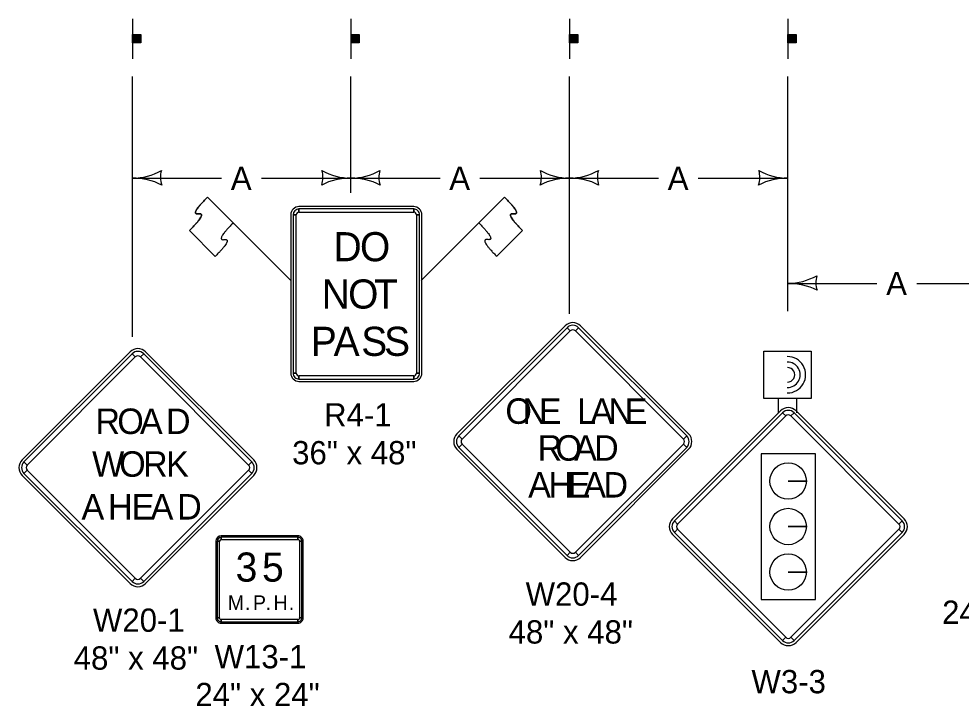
# Model space of a CAD drawing. Extents: x 10124 to 16850, y 7924 to 12166.
# Drawn here: x 13696 to 14343, y 8822 to 9294 of the extents above; entities that cross this region are included whole.
import ezdxf

# ---------------------------------------------------------------- set-up
doc = ezdxf.new("R2010")
doc.units = 0
for name, color, linetype in [('dsnStdLabel', 7, 'Continuous'), ('Level 2', 7, 'Continuous'), ('Level 5', 7, 'Continuous')]:
    doc.layers.add(name, color=color, linetype=linetype)

msp = doc.modelspace()

# ---------------------------------------------------------------- linework, layer by layer
at = {"layer": 'dsnStdLabel'}
for p, q in [((13883.12, 9114.52), (13825.78, 9171.82)), ((13825.78, 9171.82), (13843.47, 9154.14)), ((13972.41, 9114.52), (14029.73, 9171.84)), ((14029.73, 9171.84), (14012.05, 9154.15)), ((13967.36, 9165.28), (13888.61, 9165.28)), ((13888.61, 9161.53), (13888.61, 9163.72)), ((13967.36, 9163.72), (13967.36, 9161.53)), ((13882.98, 9159.65), (13882.98, 9050.9)), ((13884.55, 9159.65), (13886.73, 9159.65)), ((13969.23, 9159.65), (13971.42, 9159.65)), ((13972.98, 9050.9), (13972.98, 9159.65)), ((13831.09, 9131.15), (13813.41, 9148.83)), ((14024.43, 9131.17), (14042.11, 9148.85)), ((14071.32, 9083.47), (13997.07, 9009.22)), ((14072.64, 9082.14), (14074.85, 9079.93)), ((14078.39, 9079.93), (14080.6, 9082.14)), ((14156.17, 9009.22), (14081.92, 9083.47)), ((13772.7, 9065.55), (13698.45, 8991.3)), ((13857.55, 8991.3), (13783.31, 9065.55)), ((13774.03, 9064.22), (13776.24, 9062.01)), ((13779.77, 9062.01), (13781.98, 9064.22)), ((13886.73, 9050.9), (13884.55, 9050.9)), ((13888.61, 9046.84), (13888.61, 9049.03)), ((13967.36, 9049.03), (13967.36, 9046.84)), ((13971.42, 9050.9), (13969.23, 9050.9)), ((13888.61, 9045.28), (13967.36, 9045.28)), ((14219.28, 9025.04), (14145.03, 8950.79)), ((14220.61, 9023.71), (14222.82, 9021.5)), ((14226.35, 9021.5), (14228.56, 9023.71)), ((14304.13, 8950.79), (14229.89, 9025.04)), ((14000.6, 9005.68), (13998.4, 9007.89)), ((14154.84, 9007.89), (14152.63, 9005.68)), ((13998.4, 8999.94), (14000.6, 9002.15)), ((14152.63, 9002.15), (14154.84, 8999.94)), ((13997.07, 8998.61), (14071.32, 8924.37)), ((14081.92, 8924.37), (14156.17, 8998.61)), ((13701.99, 8987.77), (13699.78, 8989.98)), ((13856.23, 8989.98), (13854.02, 8987.77)), ((13698.45, 8980.69), (13772.7, 8906.45)), ((13699.78, 8982.02), (13701.99, 8984.23)), ((13783.31, 8906.45), (13857.55, 8980.69)), ((13854.02, 8984.23), (13856.23, 8982.02)), ((14236.99, 8976.82), (14224.49, 8976.82)), ((14224.49, 8976.82), (14236.99, 8976.82)), ((14148.57, 8947.25), (14146.36, 8949.46)), ((14302.81, 8949.46), (14300.6, 8947.25)), ((14146.36, 8941.51), (14148.57, 8943.72)), ((14236.99, 8945.57), (14224.49, 8945.57)), ((14224.49, 8945.57), (14236.99, 8945.57)), ((14300.6, 8943.72), (14302.81, 8941.51)), ((13831.52, 8935.42), (13831.52, 8882.92)), ((13832.46, 8935.42), (13834.02, 8935.42)), ((13887.77, 8939.17), (13835.27, 8939.17)), ((13835.27, 8936.67), (13835.27, 8938.24)), ((13887.77, 8938.24), (13887.77, 8936.67)), ((13889.02, 8935.42), (13890.59, 8935.42)), ((13891.52, 8882.92), (13891.52, 8935.42)), ((14145.03, 8940.18), (14219.28, 8865.94)), ((14229.89, 8865.94), (14304.13, 8940.18)), ((14074.85, 8927.9), (14072.64, 8925.69)), ((14080.6, 8925.69), (14078.39, 8927.9)), ((13776.24, 8909.98), (13774.03, 8907.77)), ((13781.98, 8907.77), (13779.77, 8909.98)), ((14236.99, 8914.32), (14224.49, 8914.32)), ((14224.49, 8914.32), (14236.99, 8914.32)), ((13834.02, 8882.92), (13832.46, 8882.92)), ((13835.27, 8880.11), (13835.27, 8881.67)), ((13835.27, 8879.17), (13887.77, 8879.17)), ((13887.77, 8881.67), (13887.77, 8880.11)), ((13890.59, 8882.92), (13889.02, 8882.92)), ((14222.82, 8869.47), (14220.61, 8867.26)), ((14228.56, 8867.26), (14226.35, 8869.47))]:
    msp.add_line(p, q, dxfattribs=at)
for points in [[(13967.36, 9163.72), (13888.61, 9163.72), (13888.61, 9161.53), (13967.36, 9161.53), (13967.36, 9163.72)], [(13884.55, 9159.65), (13884.55, 9050.9), (13886.73, 9050.9), (13886.73, 9159.65), (13884.55, 9159.65)], [(13971.42, 9050.9), (13971.42, 9159.65), (13969.23, 9159.65), (13969.23, 9050.9), (13971.42, 9050.9)], [(14072.64, 9082.14), (13998.4, 9007.89), (14000.6, 9005.68), (14074.85, 9079.93), (14072.64, 9082.14)], [(14154.84, 9007.89), (14080.6, 9082.14), (14078.39, 9079.93), (14152.63, 9005.68), (14154.84, 9007.89)], [(13774.03, 9064.22), (13699.78, 8989.98), (13701.99, 8987.77), (13776.24, 9062.01), (13774.03, 9064.22)], [(13856.23, 8989.98), (13781.98, 9064.22), (13779.77, 9062.01), (13854.02, 8987.77), (13856.23, 8989.98)], [(13888.61, 9046.84), (13967.36, 9046.84), (13967.36, 9049.03), (13888.61, 9049.03), (13888.61, 9046.84)], [(14220.61, 9023.71), (14146.36, 8949.46), (14148.57, 8947.25), (14222.82, 9021.5), (14220.61, 9023.71)], [(14302.81, 8949.46), (14228.56, 9023.71), (14226.35, 9021.5), (14300.6, 8947.25), (14302.81, 8949.46)], [(13998.4, 8999.94), (14072.64, 8925.69), (14074.85, 8927.9), (14000.6, 9002.15), (13998.4, 8999.94)], [(14080.6, 8925.69), (14154.84, 8999.94), (14152.63, 9002.15), (14078.39, 8927.9), (14080.6, 8925.69)], [(14243.31, 8995.43), (14205.85, 8995.43), (14205.85, 8895.54), (14243.31, 8895.54), (14243.31, 8995.43)], [(13699.78, 8982.02), (13774.03, 8907.77), (13776.24, 8909.98), (13701.99, 8984.23), (13699.78, 8982.02)], [(13781.98, 8907.77), (13856.23, 8982.02), (13854.02, 8984.23), (13779.77, 8909.98), (13781.98, 8907.77)], [(14146.36, 8941.51), (14220.61, 8867.26), (14222.82, 8869.47), (14148.57, 8943.72), (14146.36, 8941.51)], [(14228.56, 8867.26), (14302.81, 8941.51), (14300.6, 8943.72), (14226.35, 8869.47), (14228.56, 8867.26)], [(13832.46, 8935.42), (13832.46, 8882.92), (13834.02, 8882.92), (13834.02, 8935.42), (13832.46, 8935.42)], [(13887.77, 8938.24), (13835.27, 8938.24), (13835.27, 8936.67), (13887.77, 8936.67), (13887.77, 8938.24)], [(13890.59, 8882.92), (13890.59, 8935.42), (13889.02, 8935.42), (13889.02, 8882.92), (13890.59, 8882.92)], [(13835.27, 8880.11), (13887.77, 8880.11), (13887.77, 8881.67), (13835.27, 8881.67), (13835.27, 8880.11)]]:
    msp.add_lwpolyline(points, close=True, dxfattribs=at)
for centre in [(14224.49, 8976.82), (14224.49, 8945.57), (14224.49, 8914.32)]:
    msp.add_circle(centre, 12.5, dxfattribs=at)
for centre, radius, start, end in [((13888.61, 9159.65), 5.62, 90.00021, 179.99985), ((13888.61, 9159.65), 4.06, 90.00021, 179.99985), ((13967.36, 9159.65), 5.62, 0, 90.00021), ((13967.36, 9159.65), 4.06, 0, 90.00021), ((13888.61, 9159.65), 1.87, 90.00021, 179.99985), ((13967.36, 9159.65), 1.87, 0, 90.00021), ((14076.62, 9078.16), 7.5, 44.99999, 134.99974), ((14076.62, 9078.16), 5.62, 44.99999, 134.99974), ((14076.62, 9078.16), 2.5, 44.99999, 134.99974), ((13778, 9060.24), 7.5, 44.99999, 134.99974), ((13778, 9060.24), 5.62, 44.99999, 134.99974), ((13778, 9060.24), 2.5, 44.99999, 134.99974), ((13888.61, 9050.9), 5.62, 179.99985, 270.00006), ((13888.61, 9050.9), 4.06, 179.99985, 270.00006), ((13888.61, 9050.9), 1.87, 179.99985, 270.00006), ((13967.36, 9050.9), 4.06, 270.00006, 0.00027), ((13967.36, 9050.9), 1.87, 270.00006, 0.00027), ((13967.36, 9050.9), 5.62, 270.00006, 0.00027), ((14224.58, 9019.73), 7.5, 44.99999, 134.99974), ((14224.58, 9019.73), 5.62, 44.99999, 134.99974), ((14224.58, 9019.73), 2.5, 44.99999, 134.99974), ((14002.37, 9003.92), 7.5, 134.99974, 224.99995), ((14002.37, 9003.92), 5.62, 134.99974, 224.99995), ((14150.86, 9003.92), 5.62, 315.00016, 44.9998), ((14150.86, 9003.92), 7.5, 315.00016, 44.9998), ((14002.37, 9003.92), 2.5, 134.99974, 224.99995), ((14150.86, 9003.92), 2.5, 315.00016, 44.9998), ((13703.76, 8986), 7.5, 134.99974, 224.99995), ((13703.76, 8986), 5.62, 134.99974, 224.99995), ((13703.76, 8986), 2.5, 134.99974, 224.99995), ((13852.25, 8986), 2.5, 315.00016, 44.9998), ((13852.25, 8986), 5.62, 315.00016, 44.9998), ((13852.25, 8986), 7.5, 315.00016, 44.9998), ((14150.34, 8945.49), 7.5, 134.99974, 224.99995), ((14150.34, 8945.49), 5.62, 134.99974, 224.99995), ((14298.83, 8945.49), 5.62, 315.00016, 44.9998), ((14298.83, 8945.49), 7.5, 315.00016, 44.9998), ((14150.34, 8945.49), 2.5, 134.99974, 224.99995), ((14298.83, 8945.49), 2.5, 315.00016, 44.9998), ((13835.27, 8935.42), 3.75, 90.00021, 179.99985), ((13835.27, 8935.42), 2.81, 90.00021, 179.99985), ((13835.27, 8935.42), 1.25, 90.00021, 179.99985), ((13887.77, 8935.42), 3.75, 0, 90.00021), ((13887.77, 8935.42), 2.81, 0, 90.00021), ((13887.77, 8935.42), 1.25, 0, 90.00021), ((14076.62, 8929.67), 7.5, 224.99995, 315.00016), ((14076.62, 8929.67), 5.62, 224.99995, 315.00016), ((14076.62, 8929.67), 2.5, 224.99995, 315.00016), ((13778, 8911.75), 2.5, 224.99995, 315.00016), ((13778, 8911.75), 7.5, 224.99995, 315.00016), ((13778, 8911.75), 5.62, 224.99995, 315.00016), ((13835.27, 8882.92), 3.75, 179.99985, 270.00006), ((13835.27, 8882.92), 2.81, 179.99985, 270.00006), ((13835.27, 8882.92), 1.25, 179.99985, 270.00006), ((13887.77, 8882.92), 3.75, 270.00006, 0.00027), ((13887.77, 8882.92), 2.81, 270.00006, 0.00027), ((13887.77, 8882.92), 1.25, 270.00006, 0.00027), ((14224.58, 8871.24), 7.5, 224.99995, 315.00016), ((14224.58, 8871.24), 5.62, 224.99995, 315.00016), ((14224.58, 8871.24), 2.5, 224.99995, 315.00016)]:
    msp.add_arc(centre, radius, start, end, dxfattribs=at)
for points in [[(13813.41, 9148.83), (13825.78, 9161.21), (13813.41, 9159.43), (13825.78, 9171.82)], [(14042.11, 9148.85), (14029.73, 9161.22), (14042.11, 9159.45), (14029.73, 9171.84)], [(13843.47, 9154.14), (13831.1, 9141.76), (13843.46, 9143.53), (13831.09, 9131.15)], [(14012.05, 9154.15), (14024.43, 9141.77), (14012.06, 9143.54), (14024.43, 9131.17)]]:
    msp.add_open_spline(points, degree=2, dxfattribs=at)
at = {"layer": 'Level 2'}
for p, q in [((13774.28, 9294.29), (13774.28, 9266.79)), ((13924.28, 9294.29), (13924.28, 9266.79)), ((14074.28, 9294.29), (14074.28, 9266.79)), ((14224.28, 9294.29), (14224.28, 9266.79)), ((13774.69, 9277.84), (13774.69, 9283.42)), ((13774.97, 9283.42), (13774.97, 9277.84)), ((13775.23, 9277.84), (13775.23, 9283.42)), ((13775.5, 9283.42), (13775.5, 9277.84)), ((13775.72, 9277.84), (13775.72, 9283.42)), ((13775.93, 9283.42), (13775.93, 9277.84)), ((13776.27, 9277.84), (13776.27, 9283.42)), ((13776.53, 9283.42), (13776.53, 9277.84)), ((13776.75, 9277.84), (13776.73, 9283.42)), ((13777.07, 9283.42), (13777.07, 9277.84)), ((13777.45, 9277.84), (13777.45, 9283.42)), ((13777.88, 9283.42), (13777.88, 9277.84)), ((13778.1, 9277.84), (13778.08, 9283.42)), ((13778.52, 9283.42), (13778.53, 9277.84)), ((13778.74, 9277.84), (13778.74, 9283.42)), ((13779.06, 9283.42), (13779.06, 9277.84)), ((13779.28, 9277.84), (13779.28, 9283.42)), ((13779.6, 9283.42), (13779.6, 9277.84)), ((13924.69, 9277.84), (13924.69, 9283.42)), ((13924.97, 9283.42), (13924.97, 9277.84)), ((13925.23, 9277.84), (13925.23, 9283.42)), ((13925.5, 9283.42), (13925.5, 9277.84)), ((13925.72, 9277.84), (13925.72, 9283.42)), ((13925.93, 9283.42), (13925.93, 9277.84)), ((13926.27, 9277.84), (13926.27, 9283.42)), ((13926.53, 9283.42), (13926.53, 9277.84)), ((13926.75, 9277.84), (13926.73, 9283.42)), ((13927.07, 9283.42), (13927.07, 9277.84)), ((13927.45, 9277.84), (13927.45, 9283.42)), ((13927.88, 9283.42), (13927.88, 9277.84)), ((13928.1, 9277.84), (13928.08, 9283.42)), ((13928.52, 9283.42), (13928.53, 9277.84)), ((13928.74, 9277.84), (13928.74, 9283.42)), ((13929.06, 9283.42), (13929.06, 9277.84)), ((13929.28, 9277.84), (13929.28, 9283.42)), ((13929.6, 9283.42), (13929.6, 9277.84)), ((14074.69, 9277.84), (14074.69, 9283.42)), ((14074.97, 9283.42), (14074.97, 9277.84)), ((14075.23, 9277.84), (14075.23, 9283.42)), ((14075.5, 9283.42), (14075.5, 9277.84)), ((14075.72, 9277.84), (14075.72, 9283.42)), ((14075.93, 9283.42), (14075.93, 9277.84)), ((14076.27, 9277.84), (14076.27, 9283.42)), ((14076.53, 9283.42), (14076.53, 9277.84)), ((14076.75, 9277.84), (14076.73, 9283.42)), ((14077.07, 9283.42), (14077.07, 9277.84)), ((14077.45, 9277.84), (14077.45, 9283.42)), ((14077.88, 9283.42), (14077.88, 9277.84)), ((14078.1, 9277.84), (14078.08, 9283.42)), ((14078.52, 9283.42), (14078.53, 9277.84)), ((14078.74, 9277.84), (14078.74, 9283.42)), ((14079.06, 9283.42), (14079.06, 9277.84)), ((14079.28, 9277.84), (14079.28, 9283.42)), ((14079.6, 9283.42), (14079.6, 9277.84)), ((14224.69, 9277.84), (14224.69, 9283.42)), ((14224.97, 9283.42), (14224.97, 9277.84)), ((14225.23, 9277.84), (14225.23, 9283.42)), ((14225.5, 9283.42), (14225.5, 9277.84)), ((14225.72, 9277.84), (14225.72, 9283.42)), ((14225.93, 9283.42), (14225.93, 9277.84)), ((14226.26, 9277.84), (14226.26, 9283.42)), ((14226.53, 9283.42), (14226.53, 9277.84)), ((14226.75, 9277.84), (14226.73, 9283.42)), ((14227.07, 9283.42), (14227.07, 9277.84)), ((14227.45, 9277.84), (14227.45, 9283.42)), ((14227.88, 9283.42), (14227.88, 9277.84)), ((14228.1, 9277.84), (14228.08, 9283.42)), ((14228.52, 9283.42), (14228.53, 9277.84)), ((14228.74, 9277.84), (14228.74, 9283.42)), ((14229.06, 9283.42), (14229.06, 9277.84)), ((14229.28, 9277.84), (14229.28, 9283.42)), ((14229.6, 9283.42), (14229.6, 9277.84)), ((13774.28, 9075.97), (13774.28, 9254.79)), ((13924.28, 9174.79), (13924.28, 9254.79)), ((14074.28, 9091.61), (14074.28, 9254.79)), ((14224.28, 9093.49), (14224.28, 9254.79)), ((13774.28, 9184.79), (13835.45, 9184.79)), ((13862.78, 9184.79), (13924.28, 9184.79)), ((13924.28, 9184.79), (13985.45, 9184.79)), ((14012.78, 9184.79), (14074.28, 9184.79)), ((14074.28, 9184.79), (14135.45, 9184.79)), ((14162.78, 9184.79), (14224.28, 9184.79)), ((14224.28, 9112.49), (14285.45, 9112.49)), ((14312.78, 9112.49), (14374.28, 9112.49)), ((14217.74, 9033.59), (14217.74, 9023.59)), ((14230.24, 9033.59), (14230.24, 9023.59))]:
    msp.add_line(p, q, dxfattribs=at)
for points in [[(13774.37, 9277.84), (13774.37, 9283.46), (13780, 9283.46), (13780, 9277.84)], [(13924.37, 9277.84), (13924.37, 9283.46), (13930, 9283.46), (13930, 9277.84)], [(14074.37, 9277.84), (14074.37, 9283.46), (14080, 9283.46), (14080, 9277.84)], [(14224.37, 9277.84), (14224.37, 9283.46), (14230, 9283.46), (14230, 9277.84)], [(14207.74, 9033.59), (14207.74, 9066.09), (14240.24, 9066.09), (14240.24, 9033.59)]]:
    msp.add_lwpolyline(points, close=True, dxfattribs=at)
for centre, radius, start, end in [((13773.52, 9227.28), 42.5, 271.0176, 299.07249), ((13809.89, 9185.41), 16.42, 163.26665, 198.73335), ((13888.66, 9185.41), 16.42, 341.26665, 16.73335), ((13925.03, 9227.28), 42.5, 240.92751, 268.9824), ((13923.52, 9227.28), 42.5, 271.0176, 299.07249), ((13959.89, 9185.41), 16.42, 163.26665, 198.73335), ((14038.66, 9185.41), 16.42, 341.26665, 16.73335), ((14075.03, 9227.28), 42.5, 240.92751, 268.9824), ((14073.52, 9227.28), 42.5, 271.0176, 299.07249), ((14109.89, 9185.41), 16.42, 163.26665, 198.73335), ((14188.66, 9185.41), 16.42, 341.26665, 16.73335), ((14225.03, 9227.28), 42.5, 240.92751, 268.9824), ((13775.01, 9142.29), 42.5, 62.92751, 90.9824), ((13923.55, 9142.29), 42.5, 89.0176, 117.07249), ((13925.01, 9142.29), 42.5, 62.92751, 90.9824), ((14073.55, 9142.29), 42.5, 89.0176, 117.07249), ((14075.01, 9142.29), 42.5, 62.92751, 90.9824), ((14223.55, 9142.29), 42.5, 89.0176, 117.07249), ((14223.52, 9154.98), 42.5, 271.0176, 299.07249), ((14259.89, 9113.11), 16.42, 163.26665, 198.73335), ((14225.01, 9070), 42.5, 62.92751, 90.9824), ((14224, 9049.82), 12.5, 269.40414, 90.54446), ((14224, 9049.82), 12.5, 269.40414, 90.54446), ((14224, 9049.82), 8.75, 269.40414, 90.54446), ((14224, 9049.82), 5, 269.40414, 90.54446)]:
    msp.add_arc(centre, radius, start, end, dxfattribs=at)
at = {"layer": 'Level 5'}
for p, q in [((13813.41, 9148.83), (13831.09, 9131.15)), ((14042.11, 9148.85), (14024.43, 9131.17))]:
    msp.add_line(p, q, dxfattribs=at)
for points in [[(13825.78, 9171.82), (13813.41, 9159.43), (13825.78, 9161.21), (13813.41, 9148.83)], [(14029.73, 9171.84), (14042.11, 9159.45), (14029.73, 9161.22), (14042.11, 9148.85)], [(13843.47, 9154.14), (13831.1, 9141.76), (13843.46, 9143.53), (13831.09, 9131.15)], [(14012.05, 9154.15), (14024.43, 9141.77), (14012.06, 9143.54), (14024.43, 9131.17)]]:
    msp.add_open_spline(points, degree=2, dxfattribs=at)

# ---------------------------------------------------------------- texts
at = {"layer": 'dsnStdLabel'}
for s, height, p in [('D', 20, (13912.36, 9127.78)), ('O', 20, (13930.48, 9127.78)), ('N', 20, (13904.23, 9095.28)), ('O', 20, (13922.36, 9095.28)), ('T', 20, (13940.17, 9095.28)), ('P', 20, (13896.72, 9062.78)), ('A', 20, (13912.41, 9062.78)), ('S', 20, (13931.37, 9062.78)), ('S', 20, (13947.06, 9062.78)), ('O', 17.5, (14030.33, 9016.1)), ('N', 17.5, (14042.11, 9016.1)), ('E', 17.5, (14053.34, 9016.1)), ('L', 17.5, (14079.59, 9016.1)), ('A', 17.5, (14088.78, 9016.1)), ('N', 17.5, (14101.05, 9016.1)), ('E', 17.5, (14112.28, 9016.1)), ('R', 17.5, (13748.84, 9009.12)), ('O', 17.5, (13763.85, 9009.12)), ('A', 17.5, (13779.4, 9009.12)), ('D', 17.5, (13797.28, 9009.12)), ('R', 17.5, (14052.44, 8990.79)), ('O', 17.5, (14064.73, 8990.79)), ('A', 17.5, (14077.57, 8990.79)), ('D', 17.5, (14091.22, 8990.79)), ('W', 17.5, (13746.56, 8979.75)), ('O', 17.5, (13765.15, 8979.75)), ('R', 17.5, (13781.56, 8979.75)), ('K', 17.5, (13797.42, 8979.75)), ('A', 17.5, (14046, 8965.48)), ('H', 17.5, (14059.87, 8965.48)), ('E', 17.5, (14073.09, 8965.48)), ('A', 17.5, (14083.8, 8965.48)), ('D', 17.5, (14097.66, 8965.48)), ('A', 17.5, (13739.28, 8950.37)), ('H', 17.5, (13757.49, 8950.37)), ('E', 17.5, (13773.72, 8950.37)), ('A', 17.5, (13786.76, 8950.37)), ('D', 17.5, (13804.97, 8950.37)), ('3', 20, (13845.13, 8907.71)), ('5', 20, (13863.26, 8907.71)), ('M', 10, (13839.75, 8888.24)), ('P', 10, (13857, 8888.24)), ('H', 10, (13871.12, 8888.24)), ('.', 10, (13851.54, 8888.24)), ('.', 10, (13865.66, 8888.24)), ('.', 10, (13881.59, 8888.24))]:
    msp.add_text(s, height=height, dxfattribs=at).set_placement(p)
at = {"layer": 'Level 2'}
for s, p in [('A', (13841.8, 9176.79)), ('A', (13991.8, 9176.79)), ('A', (14141.8, 9176.79)), ('A', (14291.8, 9104.49)), ('R4-1', (13905.82, 9014.28)), ('36" x 48"', (13883.92, 8988.28)), ('W20-4', (14044.25, 8891.17)), ('24" x 36"', (14330.21, 8878.69)), ('W20-1', (13747.15, 8873.25)), ('48" x 48"', (14032.55, 8865.17)), ('W13-1', (13830.67, 8848.17)), ('48" x 48"', (13733.94, 8847.25)), ('W3-3', (14199.29, 8831.02)), ('24" x 24"', (13817.46, 8822.17))]:
    msp.add_text(s, height=16, dxfattribs=at).set_placement(p)

doc.saveas('drawing.dxf')
